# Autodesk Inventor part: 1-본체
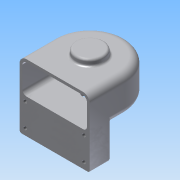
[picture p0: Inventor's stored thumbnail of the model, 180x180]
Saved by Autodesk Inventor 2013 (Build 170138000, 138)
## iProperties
Created: 2015-02
Part Number: 1-본체
Material: 알루미늄 6061
Document SubType Name: Modeling
Designer: Administrator
Density: 2.71 g/cm^3
Mass: 575.568 g
Surface Area: 707.538 cm^2
Volume: 212.387 cm^3
Author: Administrator
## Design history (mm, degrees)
sketch "스케치1"
  geometry: L1 (-50, 0)-(-50, -50); L2 (-50, -50)-(50, -50); L3 (50, -50)-(50, 0); A1 r 50 centre (0, 0) between (50, 0) and (-50, 0); 1 further point
  constraints: 6 end point, 3 tangent, 2 point on circle, 1 centre point, 1 coincident, 1 parallel, 1 perpendicular, 1 vertical
  dimensions: "d0" = 100 diameter of A1
extrude "돌출1" new body sketch "스케치1" distance "d2" = 50; taper "d3" = 0 deg
fillet "모깎기1" dims "d7" = 10
node "작업 평면1"
feature "쉘1" dims "d14" = 4
sketch "스케치4"
  geometry: L1 (-50, -20)-(-34.641, -20); L2 (34.641, -20)-(50, -20); L3 (50, -50)-(50, 0) reference; L4 (-40, -50)-(40, -50) reference; L5 (50, -50)-(40, -50) reference; L6 (-40, -50)-(-50, -50) reference; L7 (-50, 0)-(-50, -50) reference; A1 r 40 centre (0, 0) between (-34.641, -20) and (34.641, -20); 1 further point
  constraints: 4 end point, 2 point on circle, 2 point on line, 1 centre point, 1 coincident, 1 collinear, 1 horizontal
  dimensions: "d8" = 80 diameter of A1; "d10" = 30 distance between parallel lines of L6 L1; "d11" = 30 distance between parallel lines of L5 L2
extrude "돌출2" join sketch "스케치4" stored distance "d12" = 50; taper "d13" = 0 deg
sketch "스케치6"
  geometry: C1 r 25 at (0, 0); A1 r 40 centre (0, 0) between (40, 0) and (-40, 0) reference
  constraints: 1 centre point, 1 coincident
  dimensions: "d15" = 50 diameter of C1
extrude "돌출3" join sketch "스케치6" distance "d17" = 10; taper "d18" = -20 deg
hole "구멍1" diameter "d21" = 20; stored, may be unused: countersink angle "d25" = 90 deg, drill point angle "d27" = 0 deg; dims "d19" = 10, "d20" = 10, "d22" = 6, "d23" = 28, "d24" = 10, "d26" = 14
sketch "스케치7"
  geometry: C1 r 20 at (0, 0); A1 r 40 centre (0, 0) between (40, 0) and (-40, 0) reference
  constraints: 1 centre point, 1 coincident
  dimensions: "d28" = 40 diameter of C1
extrude "돌출4" join sketch "스케치7" distance "d30" = 9; taper "d31" = 0 deg
hole "구멍2" diameter "d34" = 20; stored, may be unused: countersink angle "d38" = 90 deg, drill point angle "d40" = 0 deg; dims "d32" = 10, "d33" = 10, "d35" = 6, "d36" = 28, "d37" = 8, "d39" = 10
fillet "모깎기2" dims "d41" = 3, "d42" = 0.3
fillet "모깎기3" dims "d43" = 3
chamfer "모따기1" distance "d44" = 1; stored, may be unused: second distance "d45" = 2, angle "d46" = 45 deg
sketch "스케치8"
  geometry: C1 r 21.36 at (0, 0) reference; 1 further point
  constraints: 1 horizontal alignment
  dimensions: "d47" = 18 distance of point (18, 0) C1.centre
hole "구멍3" sketch "스케치8" at (18, 0) diameter "d48" = 2.459; stored, may be unused: countersink angle "d52" = 90 deg, drill point angle "d54" = 118 deg; dims "d49" = 6, "d50" = 28, "d51" = 8, "d53" = 9
sketch "스케치9"
  geometry: L1 (-10, -92)-(-10, -10) reference; L2 (-7, -95)-(87, -95) reference; 5 further points
  constraints: 2 horizontal alignment, 2 vertical alignment
  dimensions: "d58" = 9 distance from line of L2 point (-1.75, -86); "d59" = 83.5 distance of point (81.75, -86) point (-1.75, -86); "d60" = 33 distance of point (-1.75, -86) point (-1.75, -53); "d61" = 8.25 distance from line of L1 point (-1.75, -86)
hole "구멍4" sketch "스케치9" at (-1.75, -86), (81.75, -86), (81.75, -53), (-1.75, -53) diameter "d62" = 5.134; stored, may be unused: countersink angle "d66" = 90 deg, drill point angle "d68" = 118 deg; dims "d63" = 10, "d64" = 28, "d65" = 8, "d67" = 13
node "작업 평면2"
sketch "스케치10"
  geometry: L1 (-40, 50)-(40, 50) reference; 2 further points
  constraints: 1 vertical alignment, 1 other
  dimensions: "d69" = 25 distance from line of L1 point (0, 25)
feature "엠보싱1" sketch "스케치10" dims "d0" = 100, "d70" = 0.5, "d71" = 0
node "솔리드1"
pattern_circular "원형 패턴1" dims angle "d56" = 360 deg
other parameters: "d4" = -95
